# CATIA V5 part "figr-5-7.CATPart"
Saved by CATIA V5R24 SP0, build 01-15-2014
Part number: Part1
Bounding box of the stored display mesh (mm): x 0 to 150, y -70 to 70, z -150 to 69.804
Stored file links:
  D:\KAVITA\CATIA V5-6R2014 Project_ Kavita\CATIA V5-6R2014_partfiles\Partfiles\c05_catia_v5-6r2014_prt\figr-5-7.CATPart
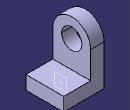
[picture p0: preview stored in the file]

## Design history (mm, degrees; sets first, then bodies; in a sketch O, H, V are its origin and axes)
Set1
  Plane1: type OffsetPt, RefPlane face of Pad2, RefPoint Sketch3
Body1 (main body)
  Sketch1 on yz-plane, origin (0, 0, 0), H (0, 1, 0), V (0, 0, 1)
    arc A1 centre (0, 0) radius 70 from (70, 0) to (-70, 0) ccw
    point P1 (70, 0)
    point P2 (-70, 0)
    line L1 (-70, 0) -> (-70, -150)
    line L2 (-70, -150) -> (70, -150)
    line L3 (70, -150) -> (70, 0)
    circle A2 centre (0, 0) radius 37.5
    radius A1 = 70
    radius A2 = 37.5
    distance O L2 = 150
    coincidence: P1 H, P2 H
    tangency: L1 A1, L3 A1
    horizontal: L2 H
  Pad1: profile Sketch1, direction (1, 0, 0), length 50
  Sketch2 on face of Pad1, origin (50, 0, 0), H (0, 1, 0), V (0, 0, 1)
    line L1 (-70, -150) -> (70, -150)
    line L2 (70, -150) -> (70, -100)
    line L3 (70, -100) -> (-70, -100)
    line L4 (-70, -100) -> (-70, -150)
    reference projected line E1 (-70, -150) -> (70, -150) from edge [face of Pad1 | face of Pad1]
    reference projected line E2 (-70, 0) -> (-70, -150) from edge [face of Pad1 | face of Pad1]
    reference projected line E3 (70, -150) -> (70, 0) from edge [face of Pad1 | face of Pad1]
    length L2 = 50
    horizontal: L1 H, L3 H
    vertical: L2 V, L4 V
    coincidence: L1 E1, E2 L4, L2 E3
  Pad2: profile Sketch2, direction (1, 0, 0), length 100
  Sketch3 on face of Pad2, origin (0, 0, -100), H (1, 0, 0), V (0, 1, 0)
    point P1 (110, 20)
